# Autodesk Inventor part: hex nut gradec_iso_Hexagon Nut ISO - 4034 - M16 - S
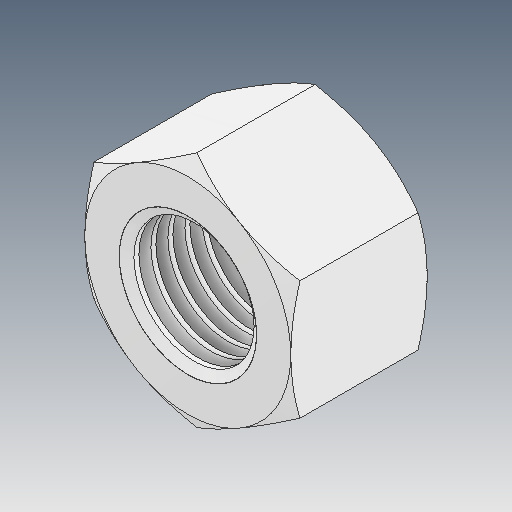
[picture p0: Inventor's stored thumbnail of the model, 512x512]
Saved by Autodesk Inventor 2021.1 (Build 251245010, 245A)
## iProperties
Created: 2021-05
Part Number: hex nut gradec_iso_Hexagon Nut ISO - 4034 - M16 - S
Material: Ogólny
Document SubType Name: Modeling
Designer: user
Density: 1 g/cm^3
Appearance: Domyślna
Author: user
Revision Number: ÈÎºÎ
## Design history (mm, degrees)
feature "ÊäÈë1"
node "Bryła1"
